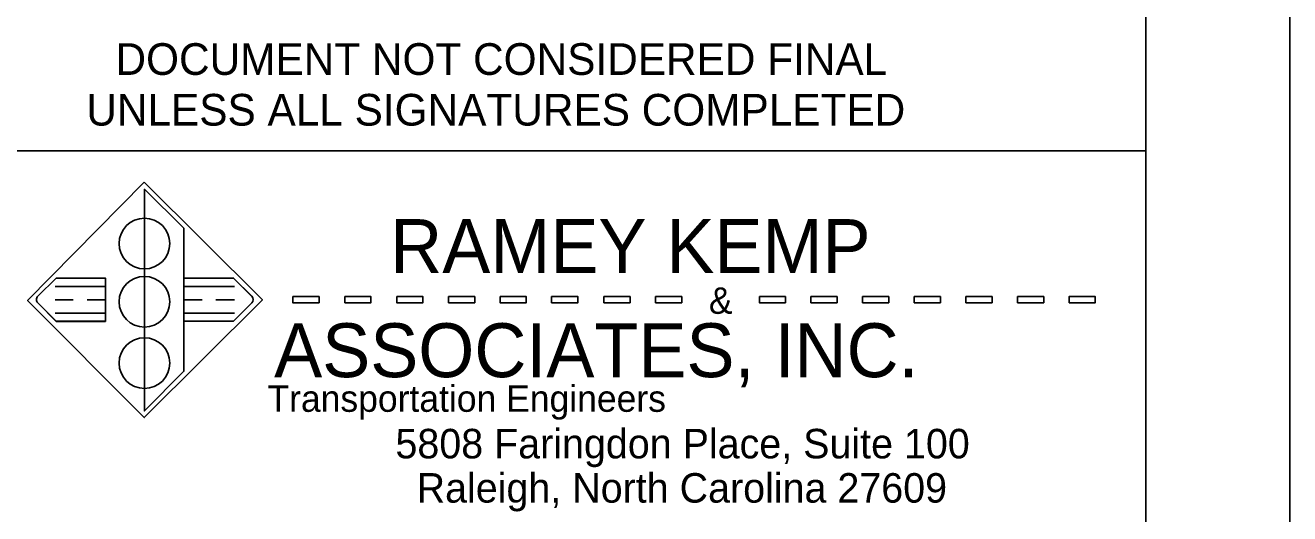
# Model space of a CAD drawing. Extents: x 573058.4 to 573116.8, y -55221.3 to -55199.3.
# Drawn here: x 573107.622 to 573112.014, y -55204.279 to -55202.584 of the extents above; entities that cross this region are included whole.
import ezdxf

# ---------------------------------------------------------------- set-up
doc = ezdxf.new("R2010")
doc.units = 0
for name, color, linetype in [('Old_Level_2', 7, 'Continuous'), ('Old_Level_4', 7, 'Continuous'), ('Sheet Plan CELL', 7, 'Continuous'), ('Sheet Plot Border Inside CELL', 7, 'Continuous'), ('Sheet Profile CELL', 7, 'Continuous'), ('Sheet Sticker Exception Certification CELL', 7, 'Continuous')]:
    doc.layers.add(name, color=color, linetype=linetype)

msp = doc.modelspace()

# ---------------------------------------------------------------- linework, layer by layer
at = {"layer": 'Old_Level_2'}
for p, q in [((573108.0362, -55203.1533), (573108.0362, -55203.9224)), ((573108.0362, -55203.1533), (573108.1731, -55203.2886)), ((573108.1731, -55203.2886), (573108.1731, -55203.7849)), ((573107.7299, -55203.4617), (573107.666, -55203.5246)), ((573107.9008, -55203.4617), (573107.7299, -55203.4617)), ((573107.9008, -55203.4617), (573107.9008, -55203.6117)), ((573108.1731, -55203.4618), (573108.3461, -55203.4618)), ((573108.3461, -55203.4618), (573108.409, -55203.5252)), ((573107.7299, -55203.611), (573107.666, -55203.548)), ((573108.3461, -55203.611), (573108.409, -55203.5476)), ((573107.9008, -55203.611), (573107.7299, -55203.611)), ((573107.9008, -55203.6117), (573107.7299, -55203.6117)), ((573108.1731, -55203.611), (573108.3461, -55203.611)), ((573108.0362, -55203.9224), (573108.1731, -55203.7849))]:
    msp.add_line(p, q, dxfattribs=at)
for points in [[(573108.0362, -55203.8445), (573108.0362, -55203.9224), (573108.1731, -55203.7849), (573108.1731, -55203.5828), (573108.1731, -55203.5366), (573108.1731, -55203.4909), (573108.1731, -55203.2886), (573108.0362, -55203.1533), (573108.0362, -55203.2538)], [(573108.0362, -55203.4295), (573108.0362, -55203.2538)], [(573108.0362, -55203.4295), (573108.0362, -55203.4556)], [(573107.9008, -55203.5828), (573107.9008, -55203.5366), (573107.9008, -55203.4909), (573107.9008, -55203.4617), (573107.7299, -55203.4617), (573107.666, -55203.5246)], [(573108.0362, -55203.6314), (573108.0362, -55203.4556)], [(573108.4087, -55203.5248), (573108.3461, -55203.4618), (573108.1731, -55203.4618), (573108.1731, -55203.4909), (573108.1731, -55203.5366), (573108.1731, -55203.5828)], [(573108.5514, -55203.526), (573108.5514, -55203.547), (573108.6429, -55203.547), (573108.6429, -55203.526), (573108.5514, -55203.526)], [(573108.7328, -55203.526), (573108.7328, -55203.547), (573108.8227, -55203.547), (573108.8227, -55203.526), (573108.7328, -55203.526)], [(573108.9124, -55203.526), (573108.9124, -55203.547), (573109.0033, -55203.547), (573109.0033, -55203.526), (573108.9124, -55203.526)], [(573109.0924, -55203.526), (573109.0924, -55203.547), (573109.1832, -55203.547), (573109.1832, -55203.526), (573109.0924, -55203.526)], [(573109.2715, -55203.526), (573109.2715, -55203.547), (573109.3625, -55203.547), (573109.3625, -55203.526), (573109.2715, -55203.526)], [(573109.4506, -55203.526), (573109.4506, -55203.547), (573109.5416, -55203.547), (573109.5416, -55203.526), (573109.4506, -55203.526)], [(573109.6319, -55203.526), (573109.6319, -55203.547), (573109.7232, -55203.547), (573109.7232, -55203.526), (573109.6319, -55203.526)], [(573109.8116, -55203.526), (573109.8116, -55203.547), (573109.9027, -55203.547), (573109.9027, -55203.526), (573109.8116, -55203.526)], [(573110.1721, -55203.526), (573110.1721, -55203.547), (573110.2628, -55203.547), (573110.2628, -55203.526), (573110.1721, -55203.526)], [(573110.3512, -55203.526), (573110.3512, -55203.547), (573110.4421, -55203.547), (573110.4421, -55203.526), (573110.3512, -55203.526)], [(573110.6215, -55203.526), (573110.5305, -55203.526), (573110.5305, -55203.547), (573110.6215, -55203.547), (573110.6215, -55203.526)], [(573110.7099, -55203.526), (573110.7099, -55203.547), (573110.8009, -55203.547), (573110.8009, -55203.526), (573110.7099, -55203.526)], [(573110.8893, -55203.526), (573110.8893, -55203.547), (573110.9803, -55203.547), (573110.9803, -55203.526), (573110.8893, -55203.526)], [(573111.0687, -55203.526), (573111.0687, -55203.547), (573111.1597, -55203.547), (573111.1597, -55203.526), (573111.0687, -55203.526)], [(573111.2481, -55203.547), (573111.339, -55203.547), (573111.339, -55203.526), (573111.2481, -55203.526), (573111.2481, -55203.547)], [(573107.666, -55203.548), (573107.7299, -55203.6117), (573107.9008, -55203.6117), (573107.9008, -55203.5828)], [(573108.1731, -55203.5828), (573108.1731, -55203.611), (573108.3461, -55203.611), (573108.4087, -55203.548)], [(573108.0362, -55203.6314), (573108.0362, -55203.6687)], [(573108.0362, -55203.8445), (573108.0362, -55203.6687)]]:
    msp.add_lwpolyline(points, dxfattribs=at)
for centre, radius, start, end in [((573108.0362, -55203.3417), 0.0879, 90, 180), ((573108.0362, -55203.3417), 0.0879, 0, 90), ((573108.0362, -55203.3417), 0.0879, 180, 270), ((573108.0362, -55203.3417), 0.0879, 270, 0), ((573108.0362, -55203.5435), 0.0879, 90, 180), ((573108.0362, -55203.5435), 0.0879, 0, 90), ((573107.6775, -55203.5363), 0.0164, 134.5812, 225.4188), ((573107.6775, -55203.5363), 0.0164, 134.5812, 225.4188), ((573108.3971, -55203.5364), 0.0164, 315.2131, 44.7869), ((573108.3971, -55203.5364), 0.0164, 315.2131, 44.7869), ((573108.0362, -55203.5435), 0.0879, 180, 270), ((573108.0362, -55203.5435), 0.0879, 270, 0), ((573108.0362, -55203.7566), 0.0879, 90, 180), ((573108.0362, -55203.7566), 0.0879, 0, 90), ((573108.0362, -55203.7566), 0.0879, 180, 270), ((573108.0362, -55203.7566), 0.0879, 270, 0)]:
    msp.add_arc(centre, radius, start, end, dxfattribs=at)
at = {"layer": 'Old_Level_4'}
for p, q in [((573108.0353, -55203.1282), (573107.6305, -55203.5389)), ((573108.0353, -55203.1282), (573108.446, -55203.5369)), ((573107.9008, -55203.4909), (573107.7257, -55203.4909)), ((573108.3485, -55203.4909), (573108.1735, -55203.4909)), ((573110.5305, -55203.547), (573110.5305, -55203.526)), ((573110.6215, -55203.526), (573110.5305, -55203.526)), ((573110.6215, -55203.547), (573110.6215, -55203.526)), ((573111.2481, -55203.547), (573111.2481, -55203.526)), ((573111.2481, -55203.526), (573111.339, -55203.526)), ((573111.339, -55203.547), (573111.339, -55203.526)), ((573108.0353, -55203.9457), (573107.6305, -55203.5389)), ((573107.789, -55203.5366), (573107.7257, -55203.5366)), ((573107.9008, -55203.5366), (573107.8369, -55203.5366)), ((573108.446, -55203.5369), (573108.0353, -55203.9457)), ((573108.2368, -55203.5366), (573108.1735, -55203.5366)), ((573108.3485, -55203.5366), (573108.2846, -55203.5366)), ((573110.5305, -55203.547), (573110.6215, -55203.547)), ((573111.2481, -55203.547), (573111.339, -55203.547)), ((573107.9008, -55203.5828), (573107.7257, -55203.5828)), ((573108.3485, -55203.5828), (573108.1735, -55203.5828))]:
    msp.add_line(p, q, dxfattribs=at)
for points in [[(573108.0353, -55203.1282), (573107.6305, -55203.5389), (573108.0353, -55203.9457), (573108.446, -55203.5369), (573108.0353, -55203.1282)], [(573108.0362, -55203.2538), (573108.0362, -55203.4295)], [(573108.0362, -55203.4556), (573108.0362, -55203.6314)], [(573108.0362, -55203.6687), (573108.0362, -55203.8445)]]:
    msp.add_lwpolyline(points, dxfattribs=at)
for points in [[(573108.5514, -55203.526), (573108.6429, -55203.526), (573108.6429, -55203.547), (573108.5514, -55203.547)], [(573108.7328, -55203.526), (573108.8227, -55203.526), (573108.8227, -55203.547), (573108.7328, -55203.547)], [(573108.9124, -55203.526), (573109.0033, -55203.526), (573109.0033, -55203.547), (573108.9124, -55203.547)], [(573109.0924, -55203.526), (573109.1832, -55203.526), (573109.1832, -55203.547), (573109.0924, -55203.547)], [(573109.2715, -55203.526), (573109.3625, -55203.526), (573109.3625, -55203.547), (573109.2715, -55203.547)], [(573109.4506, -55203.526), (573109.5416, -55203.526), (573109.5416, -55203.547), (573109.4506, -55203.547)], [(573109.6319, -55203.526), (573109.7232, -55203.526), (573109.7232, -55203.547), (573109.6319, -55203.547)], [(573109.8116, -55203.526), (573109.9027, -55203.526), (573109.9027, -55203.547), (573109.8116, -55203.547)], [(573110.1721, -55203.526), (573110.2628, -55203.526), (573110.2628, -55203.547), (573110.1721, -55203.547)], [(573110.3512, -55203.526), (573110.4421, -55203.526), (573110.4421, -55203.547), (573110.3512, -55203.547)], [(573110.7099, -55203.526), (573110.8009, -55203.526), (573110.8009, -55203.547), (573110.7099, -55203.547)], [(573110.8893, -55203.526), (573110.9803, -55203.526), (573110.9803, -55203.547), (573110.8893, -55203.547)], [(573111.0687, -55203.526), (573111.1597, -55203.526), (573111.1597, -55203.547), (573111.0687, -55203.547)]]:
    msp.add_lwpolyline(points, close=True, dxfattribs=at)
for centre in [(573108.0362, -55203.3417), (573108.0362, -55203.5435), (573108.0362, -55203.7566)]:
    msp.add_circle(centre, 0.0879, dxfattribs=at)
for centre, start, end in [((573108.0362, -55203.3417), 0, 90), ((573108.0362, -55203.3417), 270, 0), ((573108.0362, -55203.5435), 0, 90), ((573108.0362, -55203.5435), 270, 0), ((573108.0362, -55203.7566), 0, 90), ((573108.0362, -55203.7566), 270, 0)]:
    msp.add_arc(centre, 0.0879, start, end, dxfattribs=at)
at = {"layer": 'Sheet Plan CELL'}
msp.add_lwpolyline([(573111.5139, -55204.7984), (573107.5142, -55204.7984), (573107.5142, -55203.0194), (573111.5139, -55203.0194)], close=True, dxfattribs=at)
at = {"layer": 'Sheet Plot Border Inside CELL'}
msp.add_lwpolyline([(573112.0142, -55199.2984), (573078.0142, -55199.2984), (573078.0142, -55221.2984), (573112.0142, -55221.2984)], close=True, dxfattribs=at)
at = {"layer": 'Sheet Profile CELL'}
msp.add_lwpolyline([(573111.5142, -55199.7984), (573081.5142, -55199.7984), (573081.5142, -55220.7984), (573111.5142, -55220.7984)], close=True, dxfattribs=at)
at = {"layer": 'Sheet Sticker Exception Certification CELL'}
for p, q in [((573111.5149, -55202.5494), (573111.5149, -55203.0194)), ((573111.5149, -55203.0194), (573107.5142, -55203.0194))]:
    msp.add_line(p, q, dxfattribs=at)

# ---------------------------------------------------------------- texts
at = {"layer": 'Old_Level_4'}
for s, height, p in [('RAMEY KEMP', 0.18711, (573108.89, -55203.4441)), ('&', 0.0919, (573109.9967, -55203.5855)), ('ASSOCIATES, INC.', 0.187109, (573108.4867, -55203.8055)), ('Transportation Engineers', 0.092176, (573108.4635, -55203.9257)), ('5808 Faringdon Place, Suite 100', 0.102418, (573108.908, -55204.0873)), ('Raleigh, North Carolina 27609', 0.102418, (573108.9816, -55204.2409))]:
    msp.add_text(s, height=height, dxfattribs=at).set_placement(p)
at = {"layer": 'Sheet Sticker Exception Certification CELL'}
for s, p in [('DOCUMENT NOT CONSIDERED FINAL', (573107.9356, -55202.7563)), ('UNLESS ALL SIGNATURES COMPLETED', (573107.8342, -55202.9323))]:
    msp.add_text(s, height=0.11, dxfattribs=at).set_placement(p)

doc.saveas('drawing.dxf')
